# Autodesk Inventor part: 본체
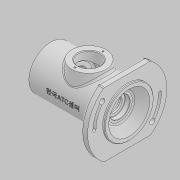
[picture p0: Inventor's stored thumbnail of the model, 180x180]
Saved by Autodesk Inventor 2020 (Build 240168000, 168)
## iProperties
Created: 2022-05
Part Number: 본체
Material: 일반
Document SubType Name: Modeling
Designer: User
Density: 1 g/cm^3
Appearance: 기본값
Author: User
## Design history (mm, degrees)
sketch "스케치1"
  geometry: L1 (0, 0)-(0, 32); L2 (0, 32)-(102, 32); L3 (102, 32)-(102, 58); L4 (102, 58)-(112, 58); L5 (112, 58)-(112, 36); L6 (112, 36)-(115, 36); L7 (115, 36)-(115, 0); L8 (115, 0)-(0, 0); L9 (8, 0)-(8, 24); L10 (8, 24)-(11, 24); L11 (11, 24)-(11, 22.5); L12 (11, 22.5)-(22, 22.5); L13 (22, 22.5)-(22, 17.5); L14 (22, 17.5)-(24.25, 17.5); L15 (24.25, 17.5)-(24.25, 18.5); L16 (24.25, 18.5)-(26, 18.5); L17 (26, 18.5)-(26, 17.5); L18 (26, 17.5)-(37, 17.5); L19 (37, 17.5)-(37, 27); L20 (37, 27)-(75, 27); L21 (75, 27)-(75, 17.5); L22 (75, 17.5)-(86, 17.5); L23 (86, 17.5)-(86, 15); L24 (86, 15)-(91, 15); L25 (91, 15)-(91, 11); L26 (91, 11)-(93.7, 11); L27 (93.7, 11)-(93.7, 15); L28 (93.7, 15)-(101, 15); L29 (101, 15)-(101, 20); L30 (101, 20)-(115, 30)
  constraints: 60 end point, 24 perpendicular, 8 point on line, 2 vertical
  dimensions: "d22" = 102 distance of L1.end L2.end; "d23" = 13 distance between parallel lines of L7 L3; "d24" = 3 distance of L5.end L6.end; "d25" = 64 diameter of L2 L8; "d26" = 72 diameter of L6 L8; "d27" = 116 diameter of L4 L8; "d28" = 48 diameter of L10 L8; "d29" = 45 diameter of L12 L8; "d30" = 37 diameter of L16 L8; "d31" = 35 diameter of L14 L8; "d32" = 54 diameter of L20 L8; "d33" = 22 diameter of L26 L8; "d34" = 60 diameter of L30.end L8; "d35" = 40 diameter of L29.end L8; "d36" = 30 diameter of L28 L8; "d37" = 14 horizontal distance of L30.end L29.end; "d39" = 5 distance of L23.end L24.end; "d40" = 29 distance between parallel lines of L7 L23; "d41" = 11 distance of L21.end L22.end; "d42" = 38 distance of L19.end L20.end; "d43" = 11 distance of L17.end L18.end; "d44" = 7.3 distance of L27.end L28.end; "d45" = 1.75 distance of L15.end L16.end; "d46" = 4 distance between parallel lines of L13 L17; "d47" = 3 distance of L9.end L10.end; "d48" = 8 distance between parallel lines of L9 L1
revolve "회전1" sketch "스케치1" stored, may be unused: angle "d49" = 90 deg
sketch "스케치2"
  geometry: L1 (-33.985, 47)-(33.985, 47); L2 (-33.985, -47)-(33.985, -47); A1 r 58 centre (0, 0) between (-33.985, 47) and (33.985, 47) reference; 1 further point
  constraints: 4 end point, 4 point on circle, 1 horizontal, 1 parallel, 1 vertical alignment
  dimensions: "d50" = 94 distance between parallel lines of L2 L1
extrude "돌출1" cut sketch "스케치2" distance "d51" = 10; taper "d52" = 0 deg
sketch "스케치4"
  geometry: L1 (0, 0)-(48, 0); L2 (0, 0)-(36.77, 30.854); L3 (0, 0)-(-36.77, -30.854); L4 (0, 0)-(-48, 0); A1 r 48 centre (0, 0) between (48, 0) and (36.77, 30.854); A2 r 52 centre (0, 0) between (52, 0) and (39.834, 33.425); A3 r 44 centre (0, 0) between (44, 0) and (33.706, 28.283); A4 r 4 centre (48, 0) between (44, 0) and (52, 0); A5 r 4 centre (36.77, 30.854) between (39.834, 33.425) and (33.706, 28.283); A6 r 48 centre (0, 0) between (-48, 0) and (-36.77, -30.854); A7 r 52 centre (0, 0) between (-52, 0) and (-39.834, -33.425); A8 r 44 centre (0, 0) between (-44, 0) and (-33.706, -28.283); A9 r 4 centre (-48, 0) between (-44, 0) and (-52, 0); A10 r 4 centre (-36.77, -30.854) between (-39.834, -33.425) and (-33.706, -28.283); A11 r 50.25 centre (0, 0) between (50.25, 0) and (38.494, 32.3); A12 r 2.25 centre (48, 0) between (45.75, 0) and (50.25, 0); A13 r 45.75 centre (0, 0) between (45.75, 0) and (35.047, 29.408); A14 r 2.25 centre (36.77, 30.854) between (38.494, 32.3) and (35.047, 29.408); A15 r 45.75 centre (0, 0) between (-45.75, 0) and (-35.047, -29.408); A16 r 2.25 centre (-48, 0) between (-45.75, 0) and (-50.25, 0); A17 r 50.25 centre (0, 0) between (-50.25, 0) and (-38.494, -32.3); A18 r 2.25 centre (-36.77, -30.854) between (-38.494, -32.3) and (-35.047, -29.408); 1 further point
  constraints: 36 point on circle, 18 centre point, 8 end point, 8 tangent, 2 coincident, 2 horizontal alignment, 6 other
  dimensions: "d62" = 48 radius of A1; "d63" = 40 deg angle of L1 L2; "d64" = 48 radius of A6; "d65" = 40 deg angle of L4 L3; "d66" = 4 radius of A5; "d67" = 4 radius of A10; "d68" = 4.5 distance of A11.end A13.end; "d69" = 4.5 distance of A15.end A17.end
extrude "돌출2" cut sketch "스케치4" extent not by distance; stored distance "d70" = 0; taper "d71" = 0 deg
extrude "돌출3" cut sketch "스케치4" distance "d72" = 4.4; taper "d73" = 0 deg
sketch "스케치5"
  geometry: C1 r 4 at (36.77, 30.854); C2 r 4 at (-36.77, -30.854); A1 r 2.25 centre (36.77, 30.854) between (38.494, 32.3) and (35.047, 29.408) reference; A2 r 2.25 centre (-36.77, -30.854) between (-38.494, -32.3) and (-35.047, -29.408) reference; 1 further point
  constraints: 2 centre point, 2 coincident
  dimensions: "d74" = 8 diameter of C1; "d75" = 8 diameter of C2
extrude "돌출4" cut sketch "스케치5" extent not by distance; stored distance "d76" = 102; taper "d77" = 0 deg
node "작업 평면1"
sketch "스케치6"
  geometry: L1 (0, 32)-(0, -32) reference; C1 r 25 at (-56, 0); 2 further points
  constraints: 1 centre point, 1 horizontal alignment, 1 midpoint
  dimensions: "d79" = 50 diameter of C1; "d80" = 56 distance from line of C1.centre L1
extrude "돌출5" join sketch "스케치6" stored distance "d81" = 4.4; taper "d82" = 5 deg
sketch "스케치7"
  geometry: C1 r 25 at (0, 0) reference; 2 further points
  constraints: 1 coincident
hole "구멍1" sketch "스케치7" at (0, 0) diameter "d83" = 32; stored, may be unused: countersink angle "d87" = 90 deg, drill point angle "d89" = 118 deg; dims "d84" = 8, "d85" = 4, "d86" = 2, "d88" = 40
sketch "스케치8"
  geometry: L1 (0, 0)-(0, 20.5); C1 r 16 at (0, 0) reference; 2 further points
  constraints: 2 end point, 1 coincident, 1 vertical
  dimensions: "d90" = 20.5 distance of L1.start L1.end
hole "구멍2" sketch "스케치8" at (0, 20.5) diameter "d91" = 2.62111; stored, may be unused: countersink angle "d95" = 90 deg, drill point angle "d97" = 118 deg; dims "d92" = 6, "d93" = 4, "d94" = 2, "d96" = 8
node "작업 평면2"
sketch "스케치9"
  geometry: L1 (61, -47)-(61, 47) reference; 2 further points
  constraints: 1 horizontal alignment, 1 other
  dimensions: "d101" = 62 distance from line of point (-1, 0) L1
feature "엠보싱1" sketch "스케치9" dims "d22" = 102, "d23" = 13, "d24" = 3, "d25" = 64, "d26" = 72, "d27" = 116, "d28" = 48, "d29" = 45, "d30" = 37, "d31" = 35, "d32" = 54, "d33" = 22, "d34" = 60, "d35" = 40, "d36" = 30, "d37" = 14, "d39" = 5, "d40" = 29, "d41" = 11, "d42" = 38, "d43" = 11, "d44" = 7.3, "d45" = 1.75, "d46" = 4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
fillet "모깎기1" dims "d104" = 0.5, "d105" = 0.6
chamfer "모따기1" distance "d106" = 0.7; stored, may be unused: second distance "d107" = 2, angle "d108" = 30 deg
fillet "모깎기2" dims "d109" = 3
chamfer "모따기2" distance "d110" = 1; stored, may be unused: second distance "d111" = 2, angle "d112" = 30 deg
sketch "스케치10"
  geometry: C1 r 32 at (0, 0) reference; 2 further points
  constraints: 1 coincident
hole "구멍3" sketch "스케치10" at (0, 0) diameter "d113" = 43.376; stored, may be unused: countersink angle "d117" = 90 deg, drill point angle "d119" = 118 deg; dims "d114" = 90, "d115" = 4, "d116" = 2, "d118" = 8
fillet "모깎기3" dims "d120" = 3
fillet "모깎기4" dims "d124" = 3
chamfer "모따기4" distance "d125" = 1; stored, may be unused: second distance "d126" = 2, angle "d127" = 30 deg
node "솔리드1"
pattern_circular "원형 패턴1" dims angle "d99" = 360 deg
feature "A9D066F2-1C7D-4E18-AEED-F7BC21143FA4" dims "d83" = 32, "d84" = 8, "d85" = 4, "d86" = 2, "d87" = 90 deg, "d88" = 40, "d89" = 118 deg
other parameters: "d78" = 38
